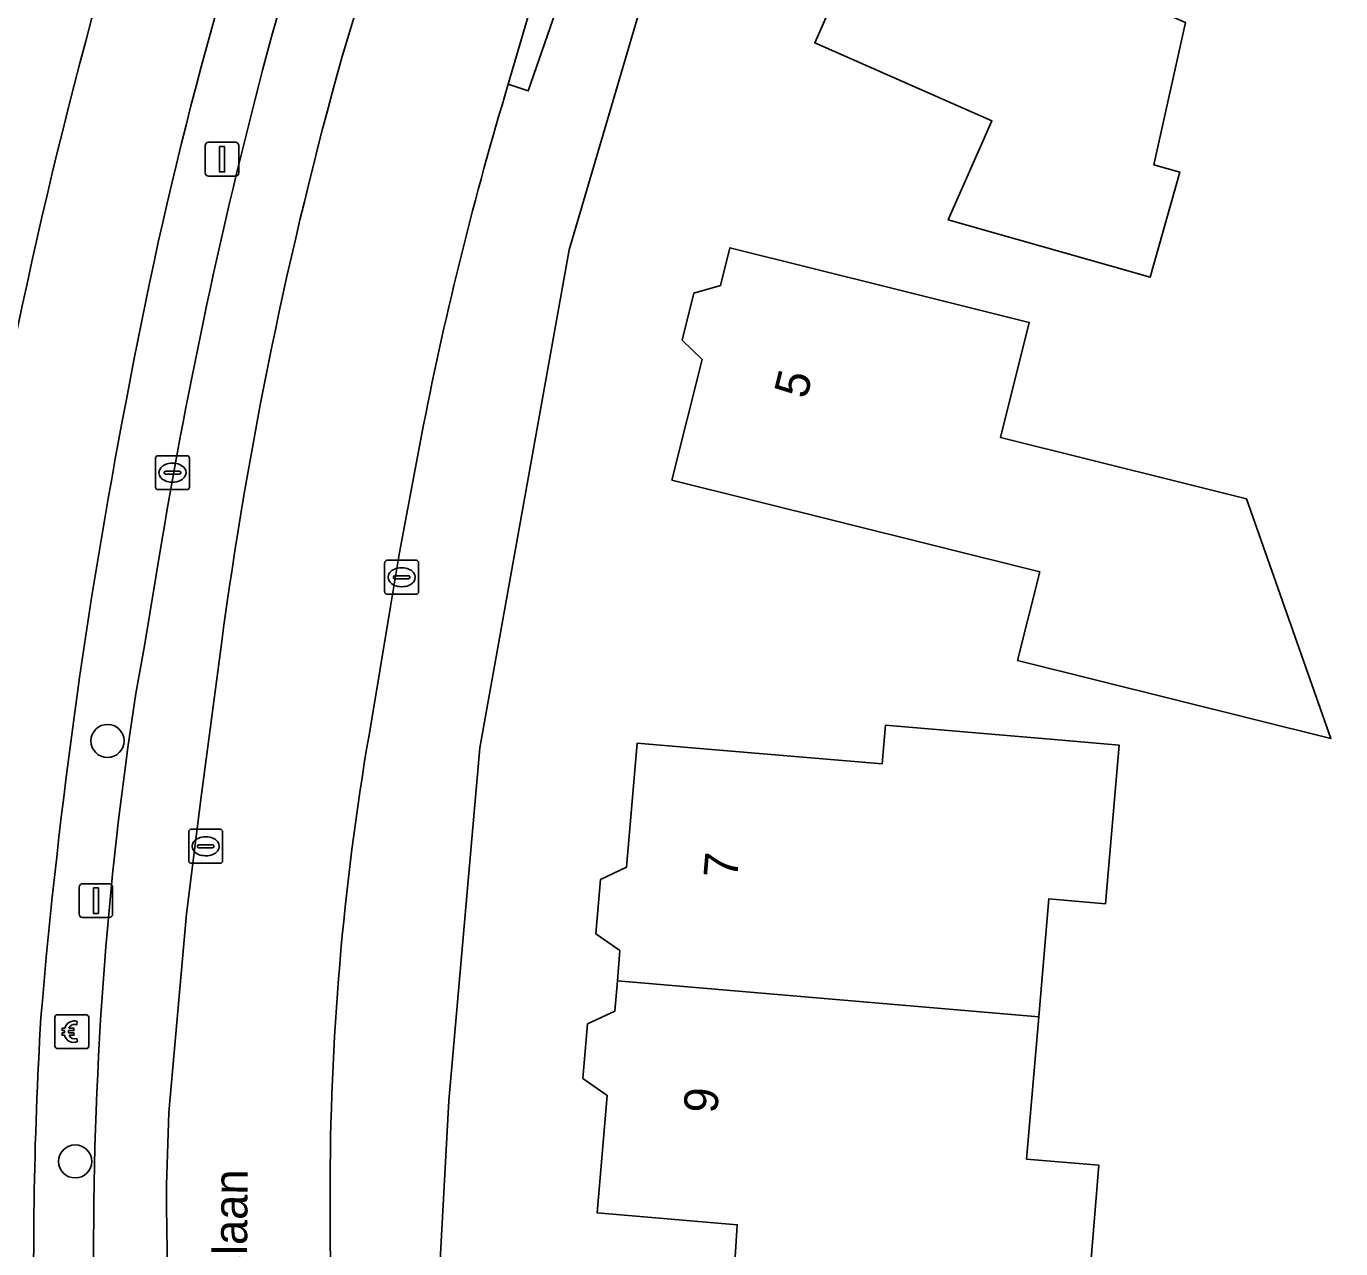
# Model space of a CAD drawing. Extents: x 161347 to 161881, y 382161 to 382804.
# Drawn here: x 161416.26 to 161455.04, y 382587.37 to 382623.43 of the extents above; entities that cross this region are included whole.
import ezdxf

# ---------------------------------------------------------------- set-up
doc = ezdxf.new("R2010")
doc.units = 0
for name, color, linetype in [('IMGEO_Betaalautomaat', 7, 'Continuous'), ('IMGEO_Boom', 7, 'Continuous'), ('IMGEO_Erf', 7, 'Continuous'), ('IMGEO_Fietspad_gesloten', 7, 'Continuous'), ('IMGEO_Groenvoorziening', 7, 'Continuous'), ('IMGEO_Kolk', 7, 'Continuous'), ('IMGEO_Lichtmast', 7, 'Continuous'), ('IMGEO_Openbare_ruimte_label', 7, 'Continuous'), ('IMGEO_Pand', 7, 'Continuous'), ('IMGEO_Pand_nummerreeks', 7, 'Continuous'), ('IMGEO_Parkeervlak_open', 7, 'Continuous'), ('IMGEO_Rijbaan_lokaal_open', 7, 'Continuous'), ('IMGEO_Rioolput', 7, 'Continuous'), ('IMGEO_Voetpad_open', 7, 'Continuous')]:
    doc.layers.add(name, color=color, linetype=linetype)

msp = doc.modelspace()

# ---------------------------------------------------------------- linework, layer by layer
at = {"layer": 'IMGEO_Betaalautomaat'}
for p, q in [((161417.107, 382593.347), (161417.107, 382594.188)), ((161417.107, 382594.188), (161417.107, 382593.347)), ((161417.182, 382594.271), (161418.023, 382594.271)), ((161418.023, 382594.271), (161417.182, 382594.271)), ((161418.106, 382594.197), (161418.106, 382593.356)), ((161418.106, 382593.356), (161418.106, 382594.197)), ((161417.39, 382593.735), (161417.39, 382593.803)), ((161417.511, 382593.803), (161417.511, 382593.735)), ((161417.769, 382594.076), (161417.752, 382593.976)), ((161417.756, 382593.57), (161417.778, 382593.483)), ((161418.032, 382593.272), (161417.191, 382593.272)), ((161417.191, 382593.272), (161418.032, 382593.272))]:
    msp.add_line(p, q, dxfattribs=at)
for points in [[(161417.39, 382593.803), (161417.321, 382593.803), (161417.321, 382593.872), (161417.4, 382593.872)], [(161417.522, 382593.872), (161417.669, 382593.872), (161417.669, 382593.803), (161417.511, 382593.803)], [(161417.395, 382593.666), (161417.321, 382593.666), (161417.321, 382593.735), (161417.39, 382593.735)], [(161417.511, 382593.735), (161417.669, 382593.735), (161417.669, 382593.666), (161417.525, 382593.666)]]:
    msp.add_lwpolyline(points, dxfattribs=at)
for centre, radius, start, end in [((161417.185, 382594.194), 0.0779, 92.4484, 184.2845), ((161417.185, 382594.194), 0.0779, 92.4484, 184.2845), ((161418.029, 382594.194), 0.0779, 2.4484, 94.2845), ((161418.029, 382594.194), 0.0779, 2.4484, 94.2845), ((161417.683, 382593.796), 0.293, 73.014, 165.0139), ((161417.689, 382593.809), 0.179, 69.3236, 159.5683), ((161417.656, 382593.721), 0.267, 191.8096, 297.0389), ((161417.689, 382593.736), 0.179, 202.7625, 291.8693), ((161417.185, 382593.35), 0.0779, 182.4484, 274.2845), ((161417.185, 382593.35), 0.0779, 182.4484, 274.2845), ((161418.029, 382593.35), 0.0779, 272.4484, 4.2845), ((161418.029, 382593.35), 0.0779, 272.4484, 4.2845)]:
    msp.add_arc(centre, radius, start, end, dxfattribs=at)
at = {"layer": 'IMGEO_Boom'}
for centre in [(161418.661, 382602.35), (161417.707, 382589.944)]:
    msp.add_circle(centre, 0.489, dxfattribs=at)
at = {"layer": 'IMGEO_Erf'}
for points in [[(161500, 382587.3), (161487.262, 382608.293), (161483.738, 382614.059), (161475.768, 382627.098), (161471.97, 382633.311), (161459.978, 382653.004), (161459.276, 382654.164), (161449.465, 382654.844), (161447.977, 382652.326), (161442.636, 382642.916), (161437.607, 382632.685), (161435.473, 382627.706), (161432.284, 382616.838), (161429.648, 382602.151), (161428.735, 382591.734), (161428.36, 382584.865)], [(161450.469, 382623.549), (161449.527, 382619.35), (161450.3, 382619.131), (161449.421, 382616.032), (161448.278, 382616.356), (161443.467, 382617.72), (161444.755, 382620.644), (161439.528, 382622.948), (161444.747, 382634.789)], [(161437.089, 382585.703), (161437.241, 382588.078), (161433.105, 382588.429), (161433.399, 382591.89), (161432.685, 382592.387), (161432.822, 382594.003), (161433.628, 382594.381), (161433.704, 382595.272), (161433.78, 382596.167), (161433.068, 382596.662), (161433.204, 382598.261), (161433.975, 382598.623), (161434.286, 382602.284), (161435.781, 382602.157), (161441.511, 382601.672), (161441.609, 382602.818), (161441.956, 382602.788), (161446.591, 382602.392), (161448.505, 382602.229), (161448.108, 382597.548), (161446.43, 382597.69), (161446.135, 382594.214), (161445.778, 382590.012), (161447.912, 382589.83), (161447.649, 382586.719)]]:
    msp.add_lwpolyline(points, dxfattribs=at)
msp.add_lwpolyline([(161445.512, 382604.727), (161446.163, 382607.341), (161440.165, 382608.837), (161435.313, 382610.048), (161436.201, 382613.608), (161435.613, 382614.177), (161435.958, 382615.56), (161436.746, 382615.785), (161437.024, 382616.9), (161441.876, 382615.689), (161445.854, 382614.696), (161445.007, 382611.301), (161450.373, 382609.963), (161452.265, 382609.491), (161454.753, 382602.422)], close=True, dxfattribs=at)
at = {"layer": 'IMGEO_Fietspad_gesloten'}
for centre, radius, start, end in [((161566.475, 382583.32), 153.669, 161.54231, 169.53098), ((161538.682, 382590.813), 121.396, 160.52887, 169.46666), ((161588, 382579.779), 171.909, 168.85604, 175.19005), ((161536.984, 382587.004), 120.503, 176.57932, 181.75761)]:
    msp.add_arc(centre, radius, start, end, dxfattribs=at)
at = {"layer": 'IMGEO_Groenvoorziening'}
msp.add_arc((161566.475, 382583.32), 153.669, 161.54231, 169.53098, dxfattribs=at)
at = {"layer": 'IMGEO_Kolk'}
for p, q in [((161420.077, 382609.838), (161420.077, 382610.69)), ((161420.152, 382610.764), (161421.004, 382610.764)), ((161420.565, 382610.544), (161420.59, 382610.544)), ((161421.078, 382610.69), (161421.078, 382609.838)), ((161420.336, 382610.258), (161420.336, 382610.27)), ((161420.774, 382610.221), (161420.376, 382610.221)), ((161420.379, 382610.307), (161420.777, 382610.307)), ((161420.82, 382610.27), (161420.82, 382610.258)), ((161421.004, 382609.764), (161420.152, 382609.764)), ((161420.588, 382609.984), (161420.563, 382609.984)), ((161426.837, 382606.753), (161426.837, 382607.605)), ((161426.912, 382607.679), (161427.764, 382607.679)), ((161427.325, 382607.459), (161427.35, 382607.459)), ((161427.838, 382607.605), (161427.838, 382606.753)), ((161427.096, 382607.173), (161427.096, 382607.185)), ((161427.534, 382607.136), (161427.136, 382607.136)), ((161427.139, 382607.222), (161427.537, 382607.222)), ((161427.58, 382607.185), (161427.58, 382607.173)), ((161427.764, 382606.679), (161426.912, 382606.679)), ((161427.348, 382606.899), (161427.323, 382606.899))]:
    msp.add_line(p, q, dxfattribs=at)
for points in [[(161420.077, 382609.838), (161420.077, 382610.69)], [(161420.152, 382610.764), (161421.004, 382610.764)], [(161421.078, 382610.69), (161421.078, 382609.838)], [(161421.004, 382609.764), (161420.152, 382609.764)], [(161426.837, 382606.753), (161426.837, 382607.605)], [(161426.912, 382607.679), (161427.764, 382607.679)], [(161427.838, 382607.605), (161427.838, 382606.753)], [(161427.764, 382606.679), (161426.912, 382606.679)]]:
    msp.add_lwpolyline(points, dxfattribs=at)
for centre, radius, start, end in [((161420.154, 382610.688), 0.0765, 91.552, 178.448), ((161420.154, 382610.688), 0.0765, 91.552, 178.448), ((161421.002, 382610.688), 0.0765, 1.552, 88.448), ((161421.002, 382610.688), 0.0765, 1.552, 88.448), ((161420.376, 382610.267), 0.0403, 85.8775, 175.7526), ((161420.373, 382610.257), 0.0366, 178.938, 274.7102), ((161420.777, 382610.264), 0.043, 264.8664, 352.4533), ((161420.781, 382610.269), 0.0386, 1.7309, 96.639), ((161420.154, 382609.84), 0.0765, 181.552, 268.448), ((161420.154, 382609.84), 0.0765, 181.552, 268.448), ((161421.002, 382609.84), 0.0765, 271.552, 358.448), ((161421.002, 382609.84), 0.0765, 271.552, 358.448), ((161426.914, 382607.603), 0.0765, 91.552, 178.448), ((161426.914, 382607.603), 0.0765, 91.552, 178.448), ((161427.762, 382607.603), 0.0765, 1.552, 88.448), ((161427.762, 382607.603), 0.0765, 1.552, 88.448), ((161427.136, 382607.182), 0.0403, 85.8775, 175.7526), ((161427.133, 382607.172), 0.0366, 178.938, 274.7102), ((161427.537, 382607.179), 0.043, 264.8664, 352.4533), ((161427.541, 382607.184), 0.0386, 1.7309, 96.639), ((161426.914, 382606.755), 0.0765, 181.552, 268.448), ((161426.914, 382606.755), 0.0765, 181.552, 268.448), ((161427.762, 382606.755), 0.0765, 271.552, 358.448), ((161427.762, 382606.755), 0.0765, 271.552, 358.448)]:
    msp.add_arc(centre, radius, start, end, dxfattribs=at)
for centre, major_axis, ratio, start_param, end_param in [((161420.564, 382610.264), (-0.387, 0.002), 0.722429, 4.712389, 7.853982), ((161420.589, 382610.264), (-0.39, 0.002), 0.717154, 1.570796, 4.712389), ((161427.324, 382607.179), (-0.387, 0.002), 0.722429, 4.712389, 7.853982), ((161427.349, 382607.179), (-0.39, 0.002), 0.717154, 1.570796, 4.712389)]:
    msp.add_ellipse(centre, major_axis=major_axis, ratio=ratio, start_param=start_param, end_param=end_param, dxfattribs=at)
at = {"layer": 'IMGEO_Lichtmast'}
for p, q in [((161421.542, 382619.113), (161421.542, 382619.913)), ((161421.542, 382619.913), (161421.542, 382619.113)), ((161421.642, 382620.013), (161422.432, 382620.013)), ((161422.432, 382620.013), (161421.642, 382620.013)), ((161422.532, 382619.913), (161422.532, 382619.113)), ((161422.532, 382619.113), (161422.532, 382619.913)), ((161422.432, 382619.013), (161421.642, 382619.013)), ((161421.642, 382619.013), (161422.432, 382619.013)), ((161417.822, 382597.238), (161417.822, 382598.038)), ((161417.822, 382598.038), (161417.822, 382597.238)), ((161417.922, 382598.138), (161418.712, 382598.138)), ((161418.712, 382598.138), (161417.922, 382598.138)), ((161418.812, 382598.038), (161418.812, 382597.238)), ((161418.812, 382597.238), (161418.812, 382598.038)), ((161418.712, 382597.138), (161417.922, 382597.138)), ((161417.922, 382597.138), (161418.712, 382597.138))]:
    msp.add_line(p, q, dxfattribs=at)
for points in [[(161421.962, 382619.888), (161422.112, 382619.888), (161422.112, 382619.138), (161421.962, 382619.138), (161421.962, 382619.888)], [(161418.242, 382598.013), (161418.392, 382598.013), (161418.392, 382597.263), (161418.242, 382597.263), (161418.242, 382598.013)]]:
    msp.add_lwpolyline(points, dxfattribs=at)
for centre, start, end in [((161421.642, 382619.913), 90, 180), ((161421.642, 382619.913), 90, 180), ((161422.432, 382619.913), 0, 90), ((161422.432, 382619.913), 360, 90), ((161421.642, 382619.113), 180, 270), ((161421.642, 382619.113), 180, 270), ((161422.432, 382619.113), 270, 0), ((161422.432, 382619.113), 270, 0), ((161417.922, 382598.038), 90, 180), ((161417.922, 382598.038), 90, 180), ((161418.712, 382598.038), 0, 90), ((161418.712, 382598.038), 360, 90), ((161417.922, 382597.238), 180, 270), ((161417.922, 382597.238), 180, 270), ((161418.712, 382597.238), 270, 0), ((161418.712, 382597.238), 270, 0)]:
    msp.add_arc(centre, 0.1, start, end, dxfattribs=at)
at = {"layer": 'IMGEO_Pand'}
for points in [[(161451.167, 382630.827), (161450.373, 382631.183), (161451.936, 382634.668), (161451.446, 382634.884), (161451.593, 382635.204), (161446.013, 382637.661), (161445.106, 382637.288), (161444.392, 382635.668), (161444.747, 382634.789), (161439.528, 382622.948), (161444.755, 382620.644), (161443.467, 382617.72), (161448.278, 382616.356), (161449.421, 382616.032), (161450.3, 382619.131), (161449.527, 382619.35), (161450.469, 382623.549), (161448.319, 382624.476)], [(161445.512, 382604.727), (161454.753, 382602.422), (161452.265, 382609.491), (161450.373, 382609.963), (161445.007, 382611.301), (161445.854, 382614.696), (161441.876, 382615.689), (161437.024, 382616.9), (161436.746, 382615.785), (161435.958, 382615.56), (161435.613, 382614.177), (161436.201, 382613.608), (161435.313, 382610.048), (161440.165, 382608.837), (161446.163, 382607.341)], [(161446.135, 382594.214), (161446.43, 382597.69), (161448.108, 382597.548), (161448.505, 382602.229), (161446.591, 382602.392), (161441.956, 382602.788), (161441.609, 382602.818), (161441.511, 382601.672), (161435.781, 382602.157), (161434.286, 382602.284), (161433.975, 382598.623), (161433.204, 382598.261), (161433.068, 382596.662), (161433.78, 382596.167), (161433.704, 382595.272)], [(161446.135, 382594.214), (161433.704, 382595.272), (161433.628, 382594.381), (161432.822, 382594.003), (161432.685, 382592.387), (161433.399, 382591.89), (161433.105, 382588.429), (161437.241, 382588.078), (161437.089, 382585.703), (161437.068, 382585.372), (161442.854, 382585.342), (161447.913, 382585.315), (161450.074, 382585.304), (161450.169, 382586.428), (161448.314, 382586.642), (161448.029, 382586.675), (161447.649, 382586.719), (161447.912, 382589.83), (161445.778, 382590.012)]]:
    msp.add_lwpolyline(points, close=True, dxfattribs=at)
at = {"layer": 'IMGEO_Parkeervlak_open'}
for points in [[(161420.266, 382608.258), (161419.75, 382605.157), (161419.494, 382603.75)], [(161420.398, 382589.25), (161420.466, 382591.383), (161420.991, 382597.249), (161421.425, 382600.701), (161422.022, 382605.217)]]:
    msp.add_lwpolyline(points, dxfattribs=at)
for centre, radius, start, end in [((161538.888, 382589.388), 118.054, 153.12542, 163.68978), ((161518.305, 382597.146), 98.3, 155.36041, 165.27067), ((161547.436, 382588.454), 126.529, 164.37081, 172.38674), ((161575.1, 382582.388), 156.981, 165.3316, 170.51441), ((161525.885, 382587.438), 107.635, 171.28312, 180.44594), ((161588.832, 382590.047), 168.436, 180.27111, 187.28827)]:
    msp.add_arc(centre, radius, start, end, dxfattribs=at)
at = {"layer": 'IMGEO_Rijbaan_lokaal_open'}
for points in [[(161430.485, 382621.731), (161431.464, 382625.084), (161432.748, 382628.786)], [(161426.376, 382602.524), (161427.011, 382606.32), (161427.279, 382607.907), (161427.985, 382611.673)], [(161422.022, 382605.217), (161421.425, 382600.701), (161420.991, 382597.249), (161420.466, 382591.383), (161420.398, 382589.25)], [(161425.622, 382579.153), (161425.424, 382582.334), (161425.389, 382583.279), (161425.308, 382585.424), (161425.233, 382587.422), (161425.227, 382588.939)]]:
    msp.add_lwpolyline(points, dxfattribs=at)
for centre, radius, start, end in [((161538.888, 382589.388), 118.054, 153.12542, 163.68978), ((161547.436, 382588.454), 126.529, 164.37081, 172.38674), ((161529.692, 382591.733), 103.643, 163.17561, 168.90744), ((161504.67, 382589.061), 79.443, 170.24309, 180.08793), ((161588.832, 382590.047), 168.436, 180.27111, 187.28827)]:
    msp.add_arc(centre, radius, start, end, dxfattribs=at)
at = {"layer": 'IMGEO_Rioolput'}
for p, q in [((161421.056, 382598.816), (161421.056, 382599.668)), ((161421.131, 382599.742), (161421.983, 382599.742)), ((161422.057, 382599.668), (161422.057, 382598.816)), ((161421.315, 382599.236), (161421.315, 382599.248)), ((161421.753, 382599.199), (161421.355, 382599.199)), ((161421.358, 382599.285), (161421.756, 382599.285)), ((161421.544, 382599.522), (161421.569, 382599.522)), ((161421.799, 382599.248), (161421.799, 382599.236)), ((161421.567, 382598.962), (161421.542, 382598.962)), ((161421.983, 382598.742), (161421.131, 382598.742))]:
    msp.add_line(p, q, dxfattribs=at)
for points in [[(161421.056, 382598.816), (161421.056, 382599.668)], [(161421.131, 382599.742), (161421.983, 382599.742)], [(161422.057, 382599.668), (161422.057, 382598.816)], [(161421.983, 382598.742), (161421.131, 382598.742)]]:
    msp.add_lwpolyline(points, dxfattribs=at)
for centre, radius, start, end in [((161421.133, 382599.666), 0.0765, 91.552, 178.448), ((161421.133, 382599.666), 0.0765, 91.552, 178.448), ((161421.981, 382599.666), 0.0765, 1.552, 88.448), ((161421.981, 382599.666), 0.0765, 1.552, 88.448), ((161421.355, 382599.245), 0.0403, 85.8775, 175.7526), ((161421.352, 382599.235), 0.0366, 178.938, 274.7102), ((161421.756, 382599.242), 0.043, 264.8664, 352.4533), ((161421.76, 382599.247), 0.0386, 1.7309, 96.639), ((161421.133, 382598.818), 0.0765, 181.552, 268.448), ((161421.133, 382598.818), 0.0765, 181.552, 268.448), ((161421.981, 382598.818), 0.0765, 271.552, 358.448), ((161421.981, 382598.818), 0.0765, 271.552, 358.448)]:
    msp.add_arc(centre, radius, start, end, dxfattribs=at)
for centre, major_axis, ratio, start_param, end_param in [((161421.543, 382599.242), (-0.387, 0.002), 0.722429, 4.712389, 7.853982), ((161421.568, 382599.242), (-0.39, 0.002), 0.717154, 1.570796, 4.712389)]:
    msp.add_ellipse(centre, major_axis=major_axis, ratio=ratio, start_param=start_param, end_param=end_param, dxfattribs=at)
at = {"layer": 'IMGEO_Voetpad_open'}
for points in [[(161430.088, 382568.58), (161428.803, 382579.556), (161428.36, 382584.865), (161428.735, 382591.734), (161429.648, 382602.151), (161432.284, 382616.838), (161435.473, 382627.706), (161437.607, 382632.685), (161442.636, 382642.916), (161447.977, 382652.326), (161449.465, 382654.844), (161459.276, 382654.164), (161460.971, 382656.682), (161458.13, 382660.667), (161457.876, 382661.023)], [(161432.748, 382628.786), (161433.505, 382628.531), (161431.071, 382621.53), (161430.485, 382621.731)], [(161427.985, 382611.673), (161427.279, 382607.907), (161427.011, 382606.32), (161426.376, 382602.524)], [(161419.494, 382603.75), (161419.75, 382605.157), (161420.266, 382608.258)], [(161425.227, 382588.939), (161425.233, 382587.422), (161425.308, 382585.424), (161425.389, 382583.279), (161425.424, 382582.334), (161425.622, 382579.153)]]:
    msp.add_lwpolyline(points, dxfattribs=at)
msp.add_lwpolyline([(161433.505, 382628.531), (161432.748, 382628.786), (161431.464, 382625.084), (161430.485, 382621.731), (161431.071, 382621.53)], close=True, dxfattribs=at)
for centre, radius, start, end in [((161518.305, 382597.146), 98.3, 155.36041, 165.27067), ((161538.682, 382590.813), 121.396, 160.52887, 169.46666), ((161575.1, 382582.388), 156.981, 165.3316, 170.51441), ((161529.692, 382591.733), 103.643, 163.17561, 168.90744), ((161588, 382579.779), 171.909, 168.85604, 175.19005), ((161525.885, 382587.438), 107.635, 171.28312, 180.44594), ((161504.67, 382589.061), 79.443, 170.24309, 180.08793), ((161536.984, 382587.004), 120.503, 176.57932, 181.75761)]:
    msp.add_arc(centre, radius, start, end, dxfattribs=at)

# ---------------------------------------------------------------- texts
at = {"layer": 'IMGEO_Openbare_ruimte_label'}
msp.add_text('Jacob Catslaan', height=1, rotation=89.5989, dxfattribs=at).set_placement((161422.731, 382580.488))
at = {"layer": 'IMGEO_Pand_nummerreeks'}
for s, rotation, p in [('5', 75.9799, (161439.283, 382612.411)), ('7', 85.1279, (161437.235, 382598.268)), ('9', 85.1301, (161436.645, 382591.339))]:
    msp.add_text(s, height=1, rotation=rotation, dxfattribs=at).set_placement(p)

doc.saveas('drawing.dxf')
